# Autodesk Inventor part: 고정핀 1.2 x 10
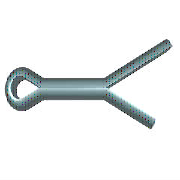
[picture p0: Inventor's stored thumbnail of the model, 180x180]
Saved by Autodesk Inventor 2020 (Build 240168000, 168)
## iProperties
Created: 2012-02
Part Number: 고정핀 1.2 x 10
Material: 강철
Description: 분할 핀
Document SubType Name: Modeling
Standard: ISO 1234
Designer: test
Standard Revision: Second edition 1997-11-01
Standards Organization: ISO
Language: ko-KR
Size Designation: 1.2 x 10
Categories: <MemberInstance><Categories><Category DisplayName="조임쇠" InternalName="e4da775c-781d-43d5-af7c-5136215cf5a6" Mnemonic="FSTN"><Category DisplayName="핀" InternalNa
Density: 7.85 g/cm^3
Appearance: 파란색 - 벽 페인트 - 광택
IsCustomPart: 1
Author: test
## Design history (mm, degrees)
sketch "스케치1"
  geometry: L1 (0, 0.5)-(5, 0.5); L2 (0, -0.5)-(5, -0.5); L3 (5, 0.5)-(10, 2.416); L4 (10, 2.416)-(10.167, 1.98); L5 (10.167, 1.98)-(5, 0); L6 (5, 0)-(12.667, -2.937); L7 (12.667, -2.937)-(12.5, -3.373); L8 (12.5, -3.373)-(5, -0.5); L9 (0, 0)-(-1.875, -0.484); L10 (0, 0)-(-1.875, 0.484); L11 (0, 0.5)-(0, -0.5); L12 (0, 0.5)-(-1.742, 0.966); L13 (0, -0.5)-(-1.742, -0.966); L14 (-3, 0)-(5, 0); L15 (5, 0.5)-(5, -0.5); A1 r 1 centre (-2, 0) between (-1.742, 0.966) and (-1.742, -0.966); A2 r 0.5 centre (-2, 0) between (-1.875, 0.484) and (-1.875, -0.484); 1 further point
  constraints: 30 end point, 5 point on circle, 4 parallel, 4 perpendicular, 4 point on line, 4 tangent, 2 centre point, 2 midpoint, 1 coincident, 1 horizontal
  dimensions: "d0" = 5 distance of L1.start L1.end (= MSIAB); "d1" = 10 horizontal distance of L1.start L3.end (= SNLG); "d2" = 159.037 deg angle of L1 L3; "d3" = 159.037 deg angle of L2 L8; "d4" = 2.5 horizontal distance of L3.end L7.end (= LGDIF); "d5" = 0.5 radius of A2 (= -0.5 x SNND1 + 0.5 x KBR); "d6" = 1 radius of A1 (= 0.5 x KBR); "d7" = 0.5 distance from line of L1 L9.start (= 0.5 x SNND1); "d8" = 0.5 distance between parallel lines of L2 L14 (= 0.5 x SNND1); "d9" = 2 distance from line of L11 A1.centre (= KOL - 0.5 x KBR)
extrude "본체" new body sketch "스케치1" stored distance "d10" = 1 (= SNND1); taper "d11" = 0 deg
workaxis "Work Axis1"
workplane "Work Plane1"
workplane "Work Plane3"
body "Solid1"
fillet "모깎기" dims "d12" = 0.35 (= 0.35 x SNND1)
other parameters: "SNND" = 1.2 [user parameter], "SNLG" = 10 [user parameter; used in 1 equation term], "SNND1" = 1 [user parameter; used in 5 equation terms], "KBR" = 2 [user parameter; used in 3 equation terms], "KOL" = 3 [user parameter; used in 1 equation term], "LGDIF" = 2.5 [user parameter; used in 1 equation term], "MSIAB" = 5 [user parameter; used in 1 equation term], "d15" = 0, "d16" = 0, "d17" = 0, "NNDMAX" = 5.5 [user parameter], "DSH" = 2.6 [user parameter], "NNDMIN" = 4.5 [user parameter]
